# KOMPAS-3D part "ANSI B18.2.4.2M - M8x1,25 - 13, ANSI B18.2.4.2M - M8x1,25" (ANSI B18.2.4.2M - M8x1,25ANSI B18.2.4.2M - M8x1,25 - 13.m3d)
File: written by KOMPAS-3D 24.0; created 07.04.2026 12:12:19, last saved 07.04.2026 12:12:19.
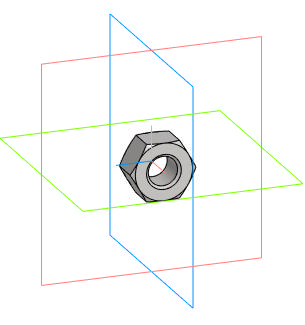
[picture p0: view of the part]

Document properties: Автор: Main; Полное имя файла: D:\DN.ru Аутсерс\Стекло смотровое DN.ru\Исходники\Стекло смотровое DN.ru SG2-34G-F тип В ГОСТ 21836-2021 Ду80 Ру16, углеродистая сталь, фланцевое\ANSI B18.2.4.2M - M8x1,25ANSI B18.2.4.2M - M8x1,25 - 13.m3d

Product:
- Body: Solid1  | qty 1
- Part/product: ANSI B18.2.4.2M - M8x1,25 - 13  | designation ANSI B18.2.4.2M - M8x1,25
    Комментарий: Типы метрических   шестигранных гаек   2
    additional columns: Сталь, мягкая

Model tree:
1. Solid1  (labels: Solid1)

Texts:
  ANSI B18.2.4.2M - M8x1,25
